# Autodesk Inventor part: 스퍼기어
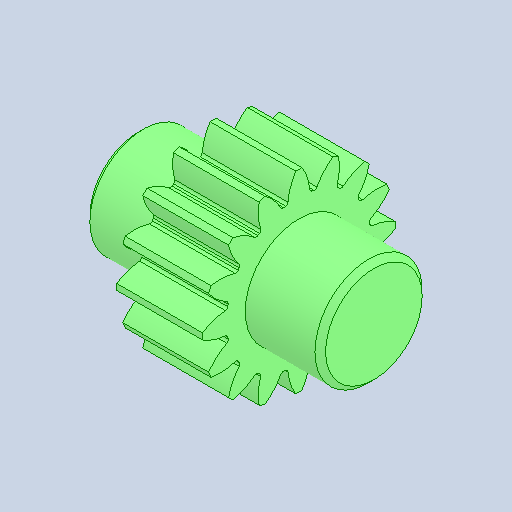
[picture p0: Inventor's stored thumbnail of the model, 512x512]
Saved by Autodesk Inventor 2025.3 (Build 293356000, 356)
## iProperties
Created: 2025-10
Part Number: 스퍼기어
Material: 강철, 합금
Document SubType Name: Modeling
Designer: PC-13
Density: 7.73 g/cm^3
Appearance: 기본값
Author: jhkim
Sending System: Autodesk Inventor 2026
Preprocessor: ST-DEVELOPER v20.1
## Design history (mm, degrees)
feature "솔리드1"
node "솔리드2"
